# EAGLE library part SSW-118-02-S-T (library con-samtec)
THROUGH-HOLE .025" SQ POST SOCKET Source: Samtec SSW.pdf
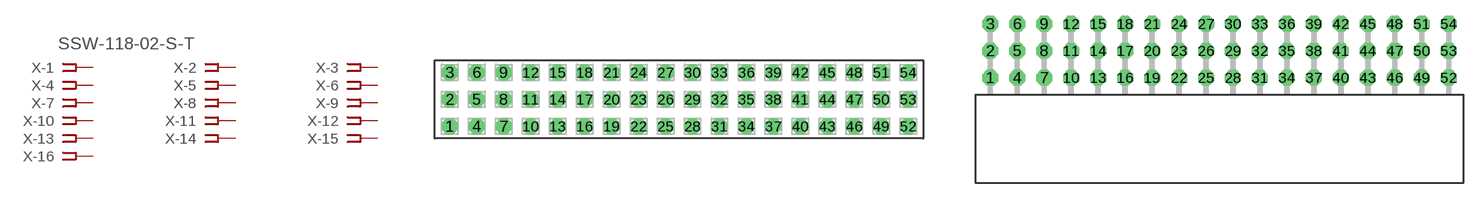
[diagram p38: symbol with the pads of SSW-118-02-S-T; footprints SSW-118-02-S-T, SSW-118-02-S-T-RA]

Designator prefix X; gates -1=FPINV -2=FPIN -3=FPIN -4=FPIN -5=FPIN -6=FPIN -7=FPIN -8=FPIN -9=FPIN -10=FPIN -11=FPIN -12=FPIN -13=FPIN -14=FPIN -15=FPIN -16=FPIN -17=FPIN -18=FPIN -19=FPIN -20=FPIN -21=FPIN -22=FPIN -23=FPIN -24=FPIN -25=FPIN -26=FPIN -27=FPIN -28=FPIN -29=FPIN -30=FPIN -31=FPIN -32=FPIN -33=FPIN -34=FPIN -35=FPIN -36=FPIN -37=FPIN -38=FPIN -39=FPIN -40=FPIN -41=FPIN -42=FPIN -43=FPIN -44=FPIN -45=FPIN -46=FPIN -47=FPIN -48=FPIN -49=FPIN -50=FPIN -51=FPIN -52=FPIN -53=FPIN -54=FPIN

## SSW-118-02-S-T (MPN: SSW-118-02-S-T; OC_FARNELL: unknown; OC_NEWARK: 82P7804)  [SSW-118-02-S-T]
1  -1:1  pas
2  -2:1  pas
3  -3:1  pas
4  -4:1  pas
5  -5:1  pas
6  -6:1  pas
7  -7:1  pas
8  -8:1  pas
9  -9:1  pas
10  -10:1  pas
11  -11:1  pas
12  -12:1  pas
13  -13:1  pas
14  -14:1  pas
15  -15:1  pas
16  -16:1  pas
17  -17:1  pas
18  -18:1  pas
19  -19:1  pas
20  -20:1  pas
21  -21:1  pas
22  -22:1  pas
23  -23:1  pas
24  -24:1  pas
25  -25:1  pas
26  -26:1  pas
27  -27:1  pas
28  -28:1  pas
29  -29:1  pas
30  -30:1  pas
31  -31:1  pas
32  -32:1  pas
33  -33:1  pas
34  -34:1  pas
35  -35:1  pas
36  -36:1  pas
37  -37:1  pas
38  -38:1  pas
39  -39:1  pas
40  -40:1  pas
41  -41:1  pas
42  -42:1  pas
43  -43:1  pas
44  -44:1  pas
45  -45:1  pas
46  -46:1  pas
47  -47:1  pas
48  -48:1  pas
49  -49:1  pas
50  -50:1  pas
51  -51:1  pas
52  -52:1  pas
53  -53:1  pas
54  -54:1  pas

## SSW-118-02-S-TRA (MPN: SSW-118-02-S-T-RA; OC_FARNELL: unknown; OC_NEWARK: 82P7805)  [SSW-118-02-S-T-RA]
Pads as for SSW-118-02-S-T

## Footprint SSW-118-02-S-T (pad centres in mm)
THROUGH-HOLE .025" SQ POST SOCKET Source: Samtec SSW.pdf
drill 1 pad 1.5 octagon: 1 -21.59,-2.54; 2 -21.59,0; 3 -21.59,2.54; 4 -19.05,-2.54; 5 -19.05,0; 6 -19.05,2.54; 7 -16.51,-2.54; 8 -16.51,0; 9 -16.51,2.54; 10 -13.97,-2.54; 11 -13.97,0; 12 -13.97,2.54; 13 -11.43,-2.54; 14 -11.43,0; 15 -11.43,2.54; 16 -8.89,-2.54; 17 -8.89,0; 18 -8.89,2.54; 19 -6.35,-2.54; 20 -6.35,0; 21 -6.35,2.54; 22 -3.81,-2.54; 23 -3.81,0; 24 -3.81,2.54; 25 -1.27,-2.54; 26 -1.27,0; 27 -1.27,2.54; 28 1.27,-2.54; 29 1.27,0; 30 1.27,2.54; 31 3.81,-2.54; 32 3.81,0; 33 3.81,2.54; 34 6.35,-2.54; 35 6.35,0; 36 6.35,2.54; 37 8.89,-2.54; 38 8.89,0; 39 8.89,2.54; 40 11.43,-2.54; 41 11.43,0; 42 11.43,2.54; 43 13.97,-2.54; 44 13.97,0; 45 13.97,2.54; 46 16.51,-2.54; 47 16.51,0; 48 16.51,2.54; 49 19.05,-2.54; 50 19.05,0; 51 19.05,2.54; 52 21.59,-2.54; 53 21.59,0; 54 21.59,2.54

## Footprint SSW-118-02-S-T-RA (pad centres in mm)
THROUGH-HOLE .025" SQ POST SOCKET Source: Samtec SSW.pdf
drill 1 pad 1.5 octagon: 1 -21.59,1.524; 2 -21.59,4.064; 3 -21.59,6.604; 4 -19.05,1.524; 5 -19.05,4.064; 6 -19.05,6.604; 7 -16.51,1.524; 8 -16.51,4.064; 9 -16.51,6.604; 10 -13.97,1.524; 11 -13.97,4.064; 12 -13.97,6.604; 13 -11.43,1.524; 14 -11.43,4.064; 15 -11.43,6.604; 16 -8.89,1.524; 17 -8.89,4.064; 18 -8.89,6.604; 19 -6.35,1.524; 20 -6.35,4.064; 21 -6.35,6.604; 22 -3.81,1.524; 23 -3.81,4.064; 24 -3.81,6.604; 25 -1.27,1.524; 26 -1.27,4.064; 27 -1.27,6.604; 28 1.27,1.524; 29 1.27,4.064; 30 1.27,6.604; 31 3.81,1.524; 32 3.81,4.064; 33 3.81,6.604; 34 6.35,1.524; 35 6.35,4.064; 36 6.35,6.604; 37 8.89,1.524; 38 8.89,4.064; 39 8.89,6.604; 40 11.43,1.524; 41 11.43,4.064; 42 11.43,6.604; 43 13.97,1.524; 44 13.97,4.064; 45 13.97,6.604; 46 16.51,1.524; 47 16.51,4.064; 48 16.51,6.604; 49 19.05,1.524; 50 19.05,4.064; 51 19.05,6.604; 52 21.59,1.524; 53 21.59,4.064; 54 21.59,6.604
